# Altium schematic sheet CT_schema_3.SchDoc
size 396 x 205 mm
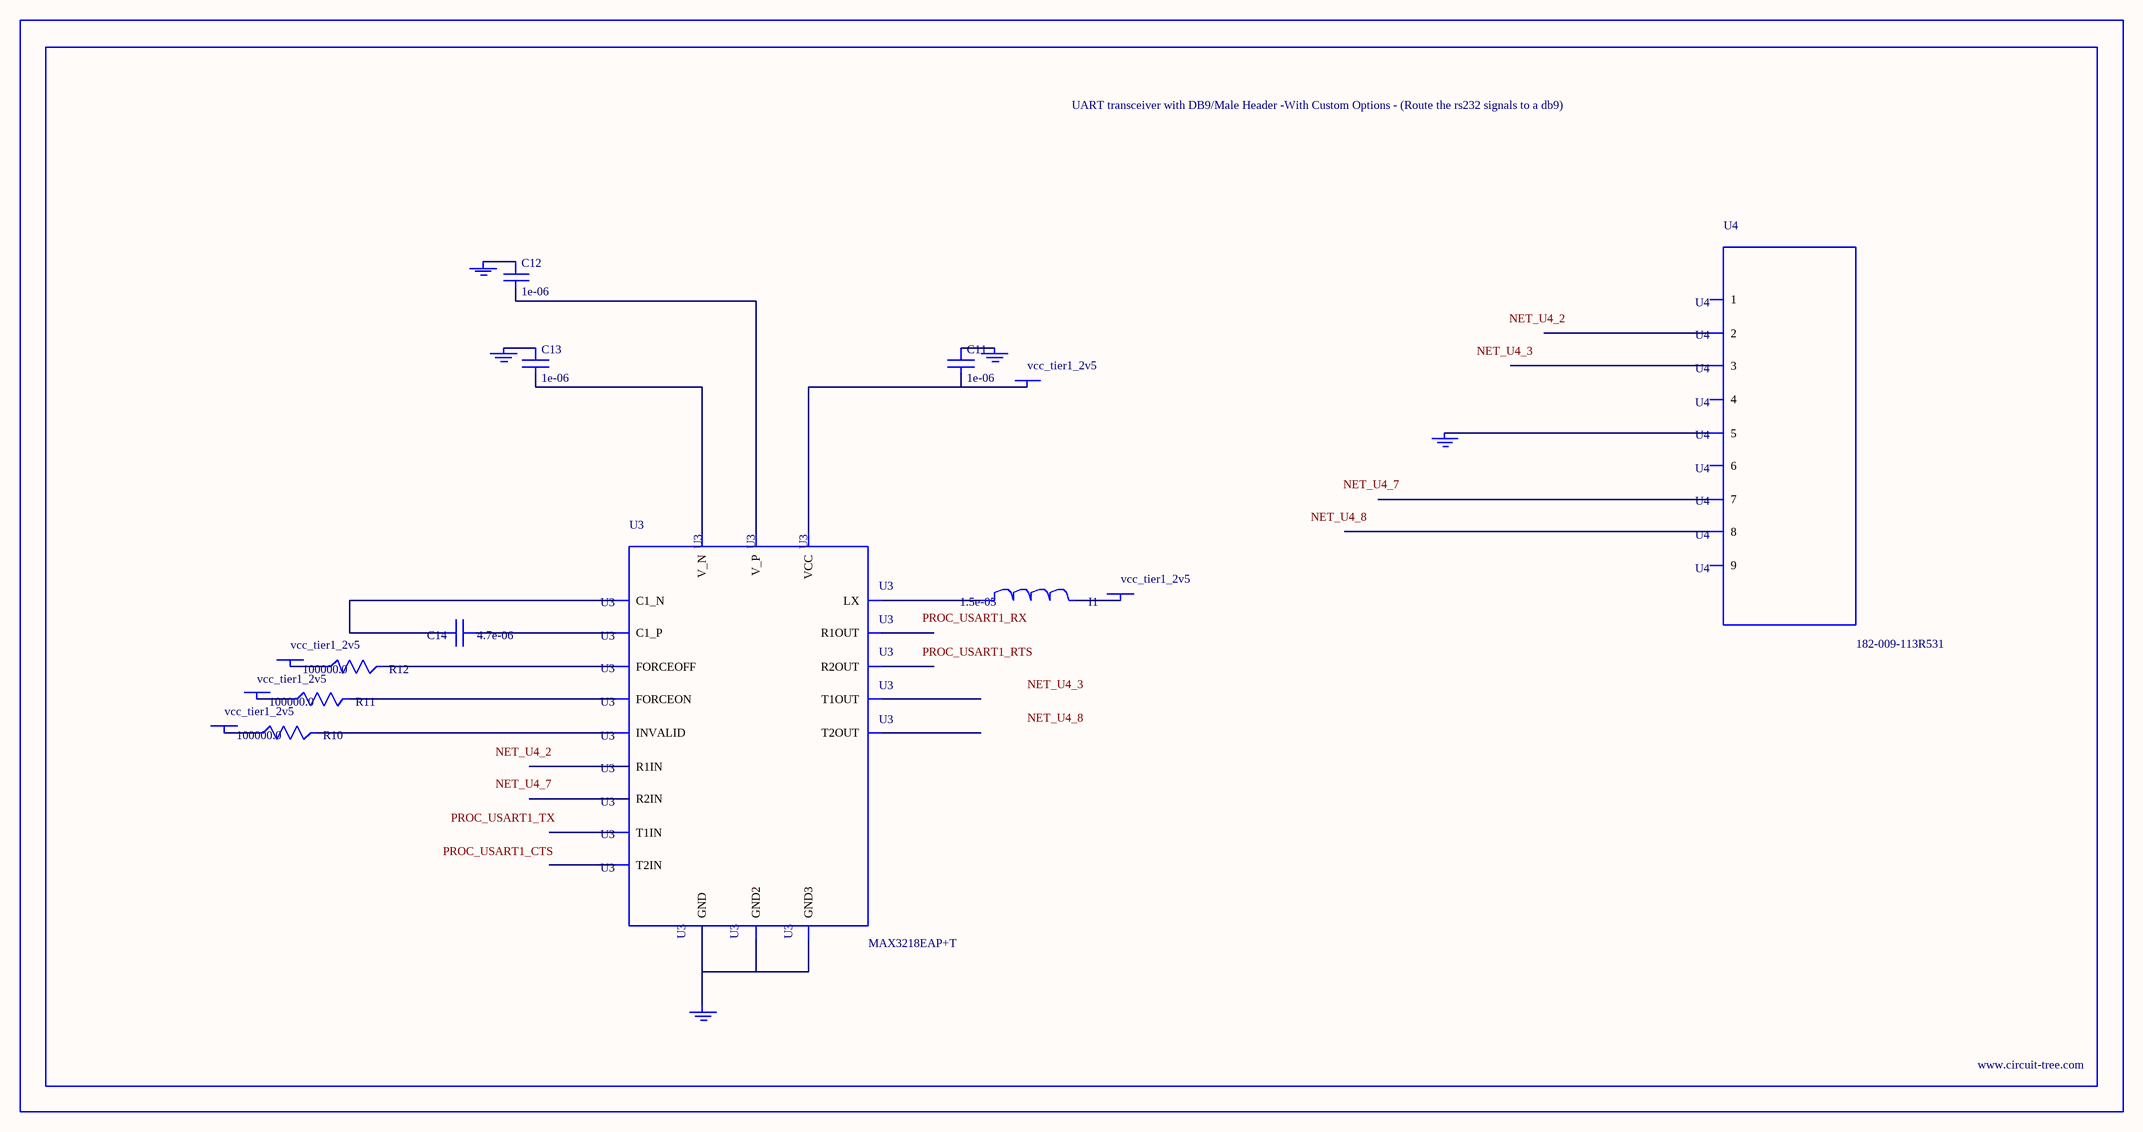
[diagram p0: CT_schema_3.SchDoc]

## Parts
BORDER2  (no value)
C11  1e-06  [C0603]
C12  1e-06  [C0603]
C13  1e-06  [C0603]
C14  4.7e-06  [C0805]
GND_INSTANCE_2_0  (no value)
GND_INSTANCE_2_1  (no value)
GND_INSTANCE_2_2  (no value)
GND_INSTANCE_2_3  (no value)
GND_INSTANCE_2_4  (no value)
I1  1.5e-05  [L1210]
POWER_INSTANCE_2_0  vcc_tier1_2v5
POWER_INSTANCE_2_1  vcc_tier1_2v5
POWER_INSTANCE_2_2  vcc_tier1_2v5
POWER_INSTANCE_2_3  vcc_tier1_2v5
POWER_INSTANCE_2_4  vcc_tier1_2v5
R10  100000.0  [R0603]
R11  100000.0  [R0603]
R12  100000.0  [R0603]
U3  MAX3218EAP+T  [SSOP-20]
U4  182-009-113R531  [182-009-MALE]

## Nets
NetC11_1: C11.1 GND_INSTANCE_2_0.0(GND)
NetC11_2: C11.2 POWER_INSTANCE_2_4.0(PWR) U3.6(VCC)
NetC12_1: C12.1 GND_INSTANCE_2_2.0(GND)
NetC12_2: C12.2 U3.19(V_P)
NetC13_1: C13.1 GND_INSTANCE_2_1.0(GND)
NetC13_2: C13.2 U3.15(V_N)
NetC14_1: C14.1 U3.18(C1_P)
NetC14_2: C14.2 U3.16(C1_N)
NetGND_INSTANCE_2_3_0: GND_INSTANCE_2_3.0(GND) U3.5(GND) U3.17(GND2) U3.20(GND3)
NetGND_INSTANCE_2_4_0: GND_INSTANCE_2_4.0(GND) U4.5
NetI1_1: I1.1 U3.1(LX)
NetI1_2: I1.2 POWER_INSTANCE_2_0.0(PWR)
NetPOWER_INSTANCE_2_1_0: POWER_INSTANCE_2_1.0(PWR) R10.1
NetPOWER_INSTANCE_2_2_0: POWER_INSTANCE_2_2.0(PWR) R11.1
NetPOWER_INSTANCE_2_3_0: POWER_INSTANCE_2_3.0(PWR) R12.1
NetR10_2: R10.2 U3.2(INVALID)
NetR11_2: R11.2 U3.3(FORCEON)
NetR12_2: R12.2 U3.4(FORCEOFF)

Not connected (* = marked no-connect by the designer): U3 7(T1IN) 8(T2IN) 9(R1OUT) 10(R2OUT) 11(R2IN) 12(R1IN) 13(T2OUT) 14(T1OUT); U4 1 2 3 4 6 7 8 9

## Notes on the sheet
- Labels drawn without touching a wire or pin: NET_U4_2, NET_U4_3, NET_U4_7, NET_U4_8, PROC_USART1_CTS, PROC_USART1_RTS, PROC_USART1_RX, PROC_USART1_TX

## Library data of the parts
BORDER2 = BORDER_PAGE2
C11-C13 = C0603C105K3RACTU
C14 = C0805C475K4RACTU
GND_INSTANCE_2_0-GND_INSTANCE_2_4 = GND
I1 = L1210R150MDWIT
POWER_INSTANCE_2_0-POWER_INSTANCE_2_4 = PWR
R10-R12 = RC0603JR-07100KL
